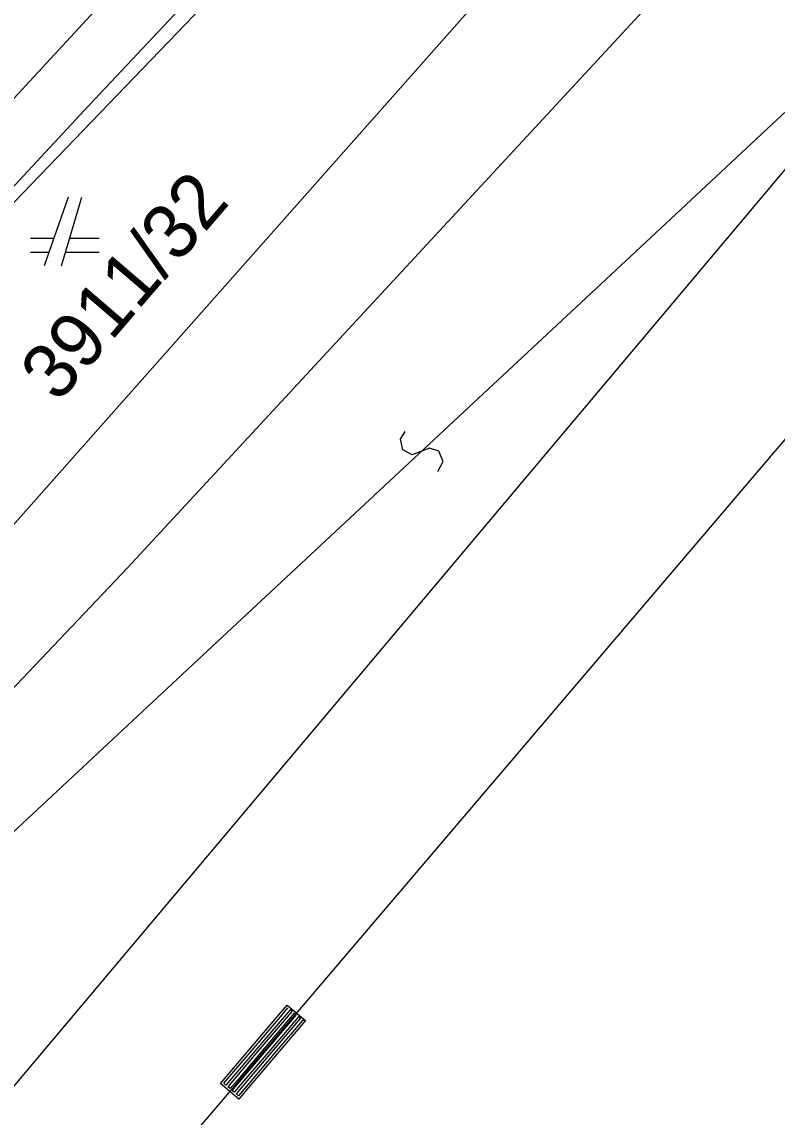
# Model space of a CAD drawing. Extents: x -266179 to -264727, y -1243225 to -1241702.
# Drawn here: x -264933.61 to -264911.6, y -1242634.87 to -1242602.96 of the extents above; entities that cross this region are included whole.
import ezdxf

# ---------------------------------------------------------------- set-up
doc = ezdxf.new("R2010")
doc.units = 0
for name, color, linetype in [('Vrstva 1', 7, 'Continuous'), ('Vrstva 19', 7, 'Continuous'), ('Vrstva 2', 7, 'Continuous'), ('Vrstva 21', 7, 'Continuous')]:
    doc.layers.add(name, color=color, linetype=linetype)

msp = doc.modelspace()

# ---------------------------------------------------------------- linework, layer by layer
at = {"layer": 'Vrstva 1'}
for p, q in [((-264950.43, -1242625.46), (-264889.07, -1242561.69)), ((-264946.23, -1242631.57), (-264886.04, -1242563.65)), ((-264885.72, -1242585), (-264932.84, -1242640.32)), ((-264913.7, -1242586.25), (-264931.79, -1242605.55)), ((-264939.76, -1242641), (-264904.75, -1242599.4)), ((-264931.79, -1242605.55), (-264950.43, -1242625.46)), ((-264932.26, -1242608.07), (-264932.96, -1242610.07)), ((-264932.46, -1242610.07), (-264931.86, -1242608.07)), ((-264932.68, -1242609.27), (-264933.36, -1242609.27)), ((-264931.36, -1242609.27), (-264932.22, -1242609.27)), ((-264933.36, -1242609.67), (-264932.82, -1242609.67)), ((-264932.34, -1242609.67), (-264931.36, -1242609.67))]:
    msp.add_line(p, q, dxfattribs=at)
at = {"layer": 'Vrstva 19'}
msp.add_line((-264885.72, -1242585), (-264932.84, -1242640.32), dxfattribs=at)
msp.add_lwpolyline([(-264925.344, -1242632.058), (-264926.167, -1242633.025), (-264926.991, -1242633.992), (-264927.289, -1242634.342), (-264927.822, -1242633.889), (-264926.999, -1242632.922), (-264926.175, -1242631.955), (-264925.877, -1242631.604), (-264925.344, -1242632.058), (-264925.43, -1242632.051), (-264926.253, -1242633.018), (-264927.076, -1242633.985), (-264927.297, -1242634.244), (-264927.358, -1242634.192), (-264926.534, -1242633.225), (-264925.711, -1242632.258), (-264925.491, -1242631.999), (-264925.552, -1242631.947), (-264926.375, -1242632.914), (-264927.198, -1242633.881), (-264927.419, -1242634.14), (-264927.48, -1242634.088), (-264926.656, -1242633.121), (-264925.833, -1242632.154), (-264925.612, -1242631.895), (-264925.673, -1242631.844), (-264926.497, -1242632.81), (-264927.32, -1242633.777), (-264927.541, -1242634.036), (-264927.601, -1242633.984), (-264926.778, -1242633.017), (-264925.955, -1242632.051), (-264925.734, -1242631.792), (-264925.795, -1242631.74), (-264926.619, -1242632.707), (-264927.442, -1242633.674), (-264927.662, -1242633.933), (-264927.723, -1242633.881), (-264926.9, -1242632.914), (-264926.076, -1242631.947), (-264925.856, -1242631.688)], dxfattribs=at)
at = {"layer": 'Vrstva 2'}
for p, q in [((-264912.25, -1242599.12), (-264930.53, -1242618.87)), ((-264904.75, -1242599.4), (-264915.43, -1242609.39)), ((-264928.88, -1242599.81), (-264942.56, -1242614.63)), ((-264915.43, -1242609.39), (-264928.49, -1242621.56)), ((-264930.53, -1242618.87), (-264944.73, -1242633.76)), ((-264928.49, -1242621.56), (-264943.5, -1242635.55))]:
    msp.add_line(p, q, dxfattribs=at)
msp.add_lwpolyline([(-264921.485, -1242616.058), (-264921.333, -1242615.766), (-264921.458, -1242615.471), (-264921.73, -1242615.384), (-264922.232, -1242615.579), (-264922.51, -1242615.427), (-264922.577, -1242615.121), (-264922.435, -1242614.892)], dxfattribs=at)
at = {"layer": 'Vrstva 21'}
msp.add_line((-264885.72, -1242585), (-264932.84, -1242640.32), dxfattribs=at)

# ---------------------------------------------------------------- texts
at = {"layer": 'Vrstva 1'}
msp.add_text('3911/32', height=1.6, rotation=49.3317, dxfattribs=at).set_placement((-264932.558, -1242614.094))

doc.saveas('drawing.dxf')
